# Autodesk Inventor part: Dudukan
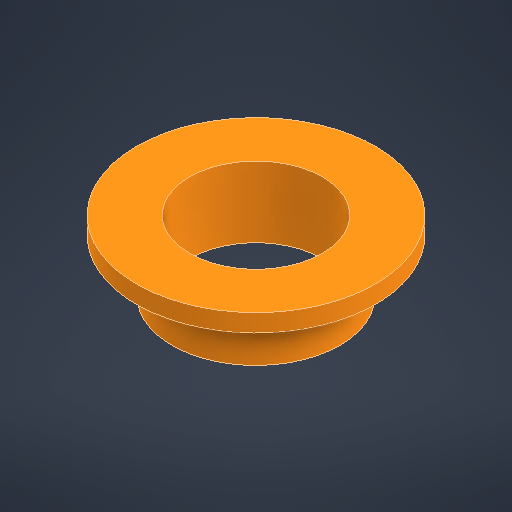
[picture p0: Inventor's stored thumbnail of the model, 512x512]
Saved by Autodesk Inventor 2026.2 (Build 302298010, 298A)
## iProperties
Created: 2021-06
Part Number: Dudukan
Material: Generic
Document SubType Name: Modeling
Designer: ASUS
Density: 1 g/cm^3
Appearance: Orange
Author: ASUS
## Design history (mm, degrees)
sketch "Sketch1"
  geometry: C1 r 13.5 at (0, 0); 1 further point
  constraints: 1 centre point, 1 coincident
  dimensions: "d0" = 27 diameter of C1
extrude "Extrusion1" new body sketch "Sketch1" distance "d1" = 2; taper "d2" = 0 deg
sketch "Sketch2"
  geometry: C1 r 9.5 at (0, 0); 1 further point
  constraints: 1 centre point, 1 coincident
  dimensions: "d3" = 19 diameter of C1
extrude "Extrusion2" join sketch "Sketch2" distance "d4" = 6; taper "d5" = 0 deg
sketch "Sketch3"
  geometry: C1 r 7.5 at (0, 0); 1 further point
  constraints: 1 centre point, 1 coincident
  dimensions: "d6" = 15 diameter of C1
extrude "Extrusion3" cut sketch "Sketch3" extent not by distance; stored distance "d7" = 0; taper "d8" = 0 deg
body "Solid1"
